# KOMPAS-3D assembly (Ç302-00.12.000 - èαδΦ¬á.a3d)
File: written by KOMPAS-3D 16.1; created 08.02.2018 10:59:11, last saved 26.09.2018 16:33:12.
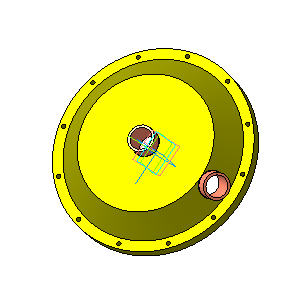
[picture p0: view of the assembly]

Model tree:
1. Плоскость под углом:1  (labels: А302-00.12.000; Полипропилен  ГОСТ 26996-86)
     Угол = -45; Расстояние = -85

Referenced files in Z:\1 ПКИ 3D\Полипропиленовые фитинги, трубы\: Труба ф40х3,7 (PN10) FV PPR ф. FV PLAST.m3d
Referenced files in Z:\Мембранные насосы\Мембранный электропривод\А302-00.00.000 - ASTRA-302 (МЭ200)\3Д\: А302-00.12.001 - Крышка.m3d
Referenced files in Z:\Мембранные насосы\Мембранный электропривод\А302-00.00.000 - ASTRA-302 (МЭ200)\Чертежи\: А302-00.12.001 - Крышка.cdw
Referenced files: graphic.tdp
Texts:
  @100~)2xA3
  (ф) А302-00.12.001 Крышка
  Труба 40 PN10 S=3,7 FV PPR ф. FV PLAST
  (-) Труба ф40х3,7 (PN10) FV PPR ф. FV PLAST (1)
  (-) Труба ф40х3,7 (PN10) FV PPR ф. FV PLAST (2)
